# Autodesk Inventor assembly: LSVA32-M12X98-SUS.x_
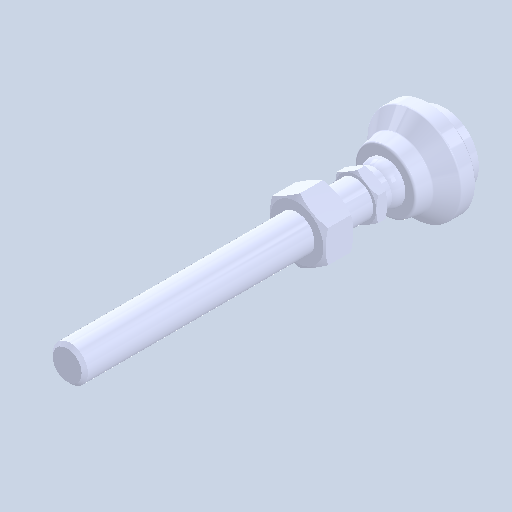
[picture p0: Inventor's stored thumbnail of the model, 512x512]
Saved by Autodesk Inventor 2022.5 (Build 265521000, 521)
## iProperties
Created: 2024-08
Part Number: LSVA32-M12X98-SUS.x_
Document SubType Name: Assembly
Designer: ImaoCorp
Author: ImaoCorp
Sending System: SOLIDWORKS 2022-2022290
MC: AMD64
MC_MODEL: Intel64 Family 6 Model 60 Stepping 3, GenuineIntel
OS: Windows_NT
FRU: Parasolid Version 33.1, build 260,  4-25-2022
FORMAT: text
GUISE: transmit
KEY: FILELSVA32-M12X98-SUS.x_t
DATE: Fri Aug 23 16:06:43 2024
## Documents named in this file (4)
- X:\14_SW2022-Inv2022\06_2024-10新製品(SME)\ELS_データ\l\lsva32-m12x98-sus\LSVA32-M12X98-SUS.x_.iam
- X:\14_SW2022-Inv2022\06_2024-10新製品(SME)\ELS_データ\l\lsva32-m12x98-sus\LSVA32-M12X98-SUS_01.ipt
- X:\14_SW2022-Inv2022\06_2024-10新製品(SME)\ELS_データ\l\lsva32-m12x98-sus\LSVA32-M12X98-SUS_02.ipt
- X:\14_SW2022-Inv2022\06_2024-10新製品(SME)\ELS_データ\l\lsva32-m12x98-sus\LSVA32-M12X98-SUS_03.ipt
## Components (3 placed, 3 different names)
1. LSVA32-M12X98-SUS_01
2. LSVA32-M12X98-SUS_02
3. LSVA32-M12X98-SUS_03
